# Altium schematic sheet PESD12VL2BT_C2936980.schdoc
size 127 x 101 mm
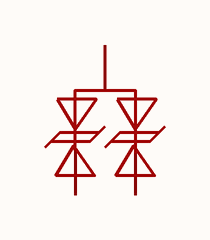
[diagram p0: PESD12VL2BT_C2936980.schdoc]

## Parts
D?  pesd12vl2bt_c2936980  [SOT-23-3_L2.9-W1.3-P1.90-LS2.4-BR]  (value not drawn)

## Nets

Not connected (* = marked no-connect by the designer): D? 1 2 3

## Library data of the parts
D? = pesd12vl2bt_c2936980: 反向截止电压(Vrwm):12V;钳位电压:10V;峰值脉冲电流(Ipp):8A@8/20us;峰值脉冲功率(Ppp):80W@8/20us;击穿电压:17.5V;; Manufacturer: TECH PUBLIC(台舟); AddInBom: yes; ModelId: c62791f0466c4ae2a892c056b845b0ca; ModelName: SOT-23-3P_L2.9-W1.3-H1.0-LS2.4-P0.95; ModelTransform: 98.425,114.173,0,180,0,0,0.0005,-0.0005,0; Reverse Stand-Off Voltage (Vrwm): 12V; Clamping Voltage: 10V; Voltage - Breakdown: 17.5V; Reverse Leakage Current (Ir): 50nA; level of protection: IEC 61000-4-4；IEC 61000-4-5；IEC 61000-4-2; Type: ESD; Junction Capacitance: 15pF；8pF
